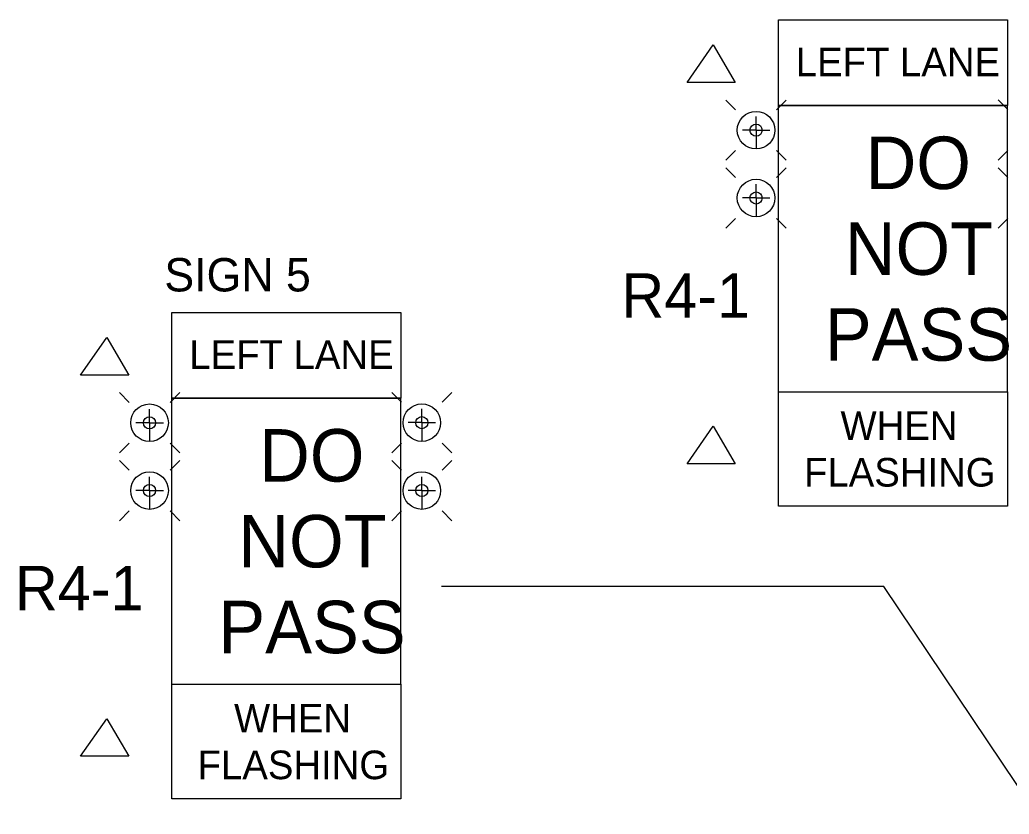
# Model space of a CAD drawing. Extents: x 15261 to 18126, y 1908 to 6555.
# Drawn here: x 16314.9 to 16480.8, y 2661.9 to 2795.2 of the extents above; entities that cross this region are included whole.
import ezdxf

# ---------------------------------------------------------------- set-up
doc = ezdxf.new("R2010")
doc.units = 0
doc.layers.add('TRAFFIC_SIGNS_PR', color=7, linetype='Continuous')
doc.layers.add('TYPICAL_TEXT_DIMEN_PR', color=7, linetype='Continuous')

msp = doc.modelspace()

# ---------------------------------------------------------------- linework, layer by layer
at = {"layer": 'TRAFFIC_SIGNS_PR'}
for p, q in [((16434.9, 2780.08), (16433.27, 2781.71)), ((16441.74, 2780.08), (16443.37, 2781.71)), ((16442.06, 2732.78), (16442.06, 2780.78)), ((16442.06, 2780.78), (16480.46, 2780.78)), ((16480.54, 2780.1), (16478.91, 2781.72)), ((16480.46, 2732.78), (16480.46, 2780.78)), ((16438.32, 2776.66), (16438.32, 2778.96)), ((16438.32, 2776.66), (16436.02, 2776.66)), ((16438.32, 2776.66), (16438.32, 2773.51)), ((16438.32, 2776.66), (16440.62, 2776.66)), ((16434.9, 2773.23), (16433.27, 2771.6)), ((16443.37, 2771.6), (16441.74, 2773.23)), ((16480.54, 2773.25), (16478.91, 2771.62)), ((16434.9, 2768.71), (16433.27, 2770.33)), ((16441.74, 2768.7), (16443.37, 2770.33)), ((16480.54, 2768.71), (16478.91, 2770.33)), ((16438.32, 2765.28), (16438.32, 2767.58)), ((16438.32, 2765.28), (16436.02, 2765.28)), ((16438.32, 2765.28), (16438.32, 2762.13)), ((16438.32, 2765.28), (16440.62, 2765.28)), ((16434.9, 2761.86), (16433.27, 2760.23)), ((16443.37, 2760.23), (16441.74, 2761.86)), ((16480.54, 2761.86), (16478.91, 2760.23)), ((16333.22, 2730.99), (16331.59, 2732.62)), ((16340.07, 2730.99), (16341.7, 2732.62)), ((16378.86, 2731.01), (16377.24, 2732.64)), ((16385.71, 2731.01), (16387.34, 2732.64)), ((16442.06, 2732.78), (16480.46, 2732.78)), ((16340.38, 2683.7), (16340.38, 2731.7)), ((16340.38, 2731.7), (16378.78, 2731.7)), ((16378.78, 2683.7), (16378.78, 2731.7)), ((16336.64, 2727.57), (16336.64, 2729.87)), ((16382.29, 2727.59), (16382.29, 2729.89)), ((16336.64, 2727.57), (16334.34, 2727.57)), ((16336.64, 2727.57), (16336.64, 2724.42)), ((16336.64, 2727.57), (16338.95, 2727.57)), ((16382.29, 2727.59), (16379.99, 2727.59)), ((16382.29, 2727.59), (16382.29, 2724.43)), ((16382.29, 2727.59), (16384.59, 2727.59)), ((16333.22, 2724.14), (16331.59, 2722.52)), ((16341.69, 2722.52), (16340.07, 2724.14)), ((16378.86, 2724.16), (16377.24, 2722.53)), ((16387.34, 2722.53), (16385.71, 2724.16)), ((16333.22, 2719.62), (16331.59, 2721.25)), ((16340.07, 2719.62), (16341.7, 2721.25)), ((16378.86, 2719.62), (16377.24, 2721.25)), ((16385.71, 2719.62), (16387.34, 2721.25)), ((16336.64, 2716.19), (16336.64, 2718.5)), ((16382.29, 2716.19), (16382.29, 2718.5)), ((16336.64, 2716.19), (16334.34, 2716.19)), ((16336.64, 2716.19), (16336.64, 2713.04)), ((16336.64, 2716.19), (16338.95, 2716.19)), ((16382.29, 2716.19), (16379.99, 2716.19)), ((16382.29, 2716.19), (16382.29, 2713.04)), ((16382.29, 2716.19), (16384.59, 2716.19)), ((16333.22, 2712.77), (16331.59, 2711.14)), ((16341.69, 2711.14), (16340.07, 2712.77)), ((16378.86, 2712.77), (16377.24, 2711.14)), ((16387.34, 2711.14), (16385.71, 2712.77)), ((16340.38, 2683.7), (16378.78, 2683.7))]:
    msp.add_line(p, q, dxfattribs=at)
for centre, radius in [((16438.32, 2776.65), 3.15), ((16438.32, 2776.65), 1.02), ((16438.32, 2765.28), 3.15), ((16438.32, 2765.28), 1.02), ((16336.64, 2727.57), 3.15), ((16382.29, 2727.58), 3.15), ((16336.64, 2727.57), 1.02), ((16382.29, 2727.58), 1.02), ((16336.64, 2716.19), 3.15), ((16382.29, 2716.19), 3.15), ((16336.64, 2716.19), 1.02), ((16382.29, 2716.19), 1.02)]:
    msp.add_circle(centre, radius, dxfattribs=at)
at = {"layer": 'TYPICAL_TEXT_DIMEN_PR'}
for p, q in [((16459.72, 2700.07), (16385.59, 2700.07)), ((16494.38, 2648.48), (16459.72, 2700.07))]:
    msp.add_line(p, q, dxfattribs=at)
for points in [[(16442.06, 2795.18), (16480.46, 2795.18), (16480.46, 2780.78), (16442.06, 2780.78)], [(16426.76, 2784.67), (16431.12, 2790.97), (16434.83, 2784.67)], [(16340.38, 2746.09), (16378.78, 2746.09), (16378.78, 2731.7), (16340.38, 2731.7)], [(16325.08, 2735.58), (16329.45, 2741.88), (16333.15, 2735.58)], [(16442.06, 2732.78), (16480.46, 2732.78), (16480.46, 2713.59), (16442.06, 2713.59)], [(16426.76, 2720.7), (16431.12, 2727.01), (16434.83, 2720.7)], [(16340.38, 2683.7), (16378.78, 2683.7), (16378.78, 2664.5), (16340.38, 2664.5)], [(16325.08, 2671.62), (16329.45, 2677.92), (16333.15, 2671.62)]]:
    msp.add_lwpolyline(points, close=True, dxfattribs=at)

# ---------------------------------------------------------------- texts
at = {"layer": 'TRAFFIC_SIGNS_PR'}
for s, height, p in [('DO', 8.8, (16456.69, 2766.78)), ('NOT', 8.8, (16453.2, 2752.38)), ('R4-1', 7.44, (16415.74, 2745.2)), ('PASS', 8.8, (16449.85, 2737.98)), ('DO', 8.8, (16355.01, 2717.7)), ('NOT', 8.8, (16351.53, 2703.3)), ('R4-1', 7.44, (16314.07, 2696.12)), ('PASS', 8.8, (16348.18, 2688.9))]:
    msp.add_text(s, height=height, dxfattribs=at).set_placement(p)
at = {"layer": 'TYPICAL_TEXT_DIMEN_PR'}
for s, height, p in [('LEFT LANE', 4.8, (16444.98, 2785.69)), ('   SIGN 5   ', 5.6, (16332.88, 2749.6)), ('LEFT LANE', 4.8, (16343.31, 2736.6)), ('WHEN', 4.8, (16452.48, 2724.69)), ('FLASHING', 4.8, (16446.37, 2716.86)), ('WHEN', 4.8, (16350.8, 2675.61)), ('FLASHING', 4.8, (16344.7, 2667.77))]:
    msp.add_text(s, height=height, dxfattribs=at).set_placement(p)

doc.saveas('drawing.dxf')
